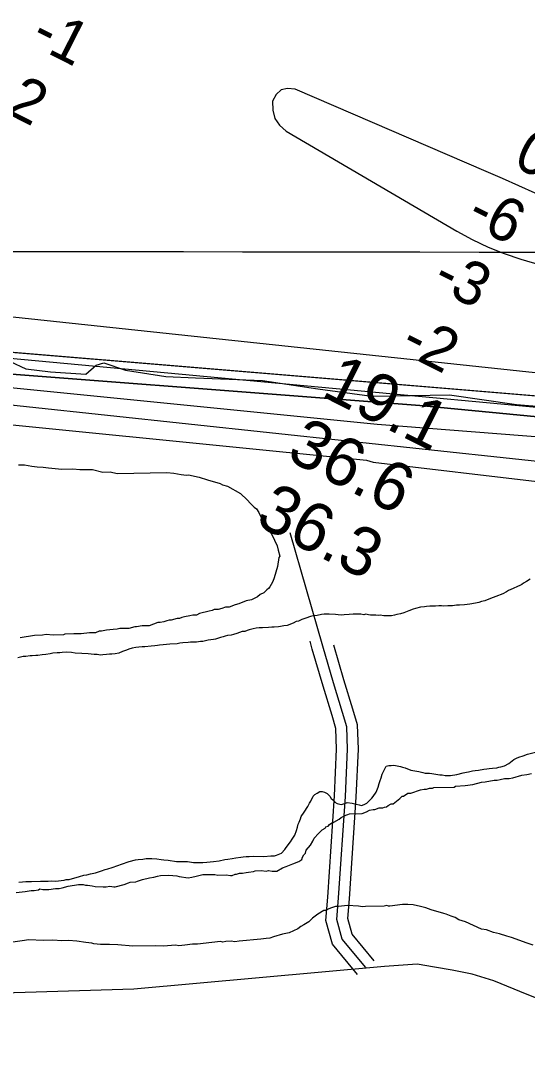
# Model space of a CAD drawing. Extents: x 3219052 to 3256913, y 800770 to 826146.
# Drawn here: x 3237159 to 3237861, y 811124 to 812545 of the extents above; entities that cross this region are included whole.
import ezdxf

# ---------------------------------------------------------------- set-up
doc = ezdxf.new("R2010")
doc.units = 0
for name, color, linetype in [('V-GRID-MAJR', 7, 'Continuous'), ('V-LEVE-TOET', 7, 'Continuous'), ('V-RIVR-EDGE', 7, 'Continuous'), ('V-RIVR-RANG', 7, 'Continuous'), ('V-ROAD-CNTR', 7, 'Continuous'), ('V-SITE-VEGE', 7, 'Continuous'), ('V-TOPO-DPTH', 7, 'Continuous'), ('V-TOPO-MAJR', 7, 'Continuous'), ('V-TOPO-MINR', 7, 'Continuous'), ('V-TOPO-SHOR', 7, 'Continuous'), ('V-TOPO-WATR', 7, 'Continuous')]:
    doc.layers.add(name, color=color, linetype=linetype)

msp = doc.modelspace()

# ---------------------------------------------------------------- linework, layer by layer
at = {"layer": 'V-GRID-MAJR'}
msp.add_spline([(3223229.222, 812245.659), (3228465.955, 812237.661), (3233702.6890000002, 812230.425), (3238939.4250000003, 812223.951), (3244176.161, 812218.238), (3249412.899, 812213.287), (3254649.637, 812209.098), (3254649.6380000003, 812209.098)], degree=3, dxfattribs=at)
at = {"layer": 'V-LEVE-TOET'}
msp.add_lwpolyline([(3238182.165, 811071.7000000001), (3237860.271, 811198.746), (3237814.414, 811217.536), (3237784.448, 811226.4720000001), (3237756.583, 811232.116), (3237732.015, 811236.265), (3237708.346, 811240.419), (3237688.88, 811239.188), (3237662.825, 811237.3470000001), (3237316.042, 811205.908), (3236864.697, 811191.961), (3236556.232, 811171.966), (3236455.3140000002, 811160.1140000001), (3236418.184, 811154.96), (3236209.219, 811099.193)], dxfattribs=at)
at = {"layer": 'V-RIVR-EDGE'}
msp.add_lwpolyline([(3237145.1445905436, 812073.8424826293), (3237166.85369583, 812063.7911809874), (3237200.7487915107, 812059.7952554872), (3237249.859715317, 812056.6310639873), (3237263.799459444, 812068.7676121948), (3237274.674971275, 812072.2181536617), (3237304.641855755, 812061.7117537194), (3237360.2600295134, 812053.3153214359), (3237401.5500003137, 812051.4745064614), (3237494.127502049, 812047.7681554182), (3237570.6026253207, 812036.2773955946), (3237645.3422669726, 812026.0949646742), (3237753.147419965, 812028.0017894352), (3237845.700200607, 812014.2978782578), (3237963.4749681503, 812004.8783922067)], dxfattribs=at)
at = {"layer": 'V-ROAD-CNTR'}
for points in [[(3237637.254688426, 811235.6885012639), (3237604.4487540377, 811275.151422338), (3237597.099768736, 811302.399367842), (3237599.44776404, 811332.0253085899), (3237608.93274507, 811472.38002788), (3237611.754739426, 811537.9258967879), (3237610.680741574, 811568.8178350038), (3237604.7837533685, 811588.630795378), (3237592.4097781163, 811629.3547139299), (3237577.4488080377, 811680.473611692), (3237532.3648982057, 811837.067298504)], [(3237625.7197114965, 811226.0995204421), (3237590.819781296, 811268.082436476), (3237581.9417990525, 811300.9983706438), (3237584.48779396, 811333.1233063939), (3237593.9547750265, 811473.2080262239), (3237596.7437694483, 811537.987896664), (3237595.7567714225, 811566.3788398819), (3237590.4187820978, 811584.310804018), (3237578.035806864, 811625.0677225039), (3237563.0438368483, 811676.2916200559), (3237559.9048431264, 811687.19459825)], [(3237648.7896653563, 811245.277482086), (3237618.07772678, 811282.2204082), (3237612.2577384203, 811303.8003650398), (3237614.4077341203, 811330.927310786), (3237623.9107151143, 811471.552029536), (3237626.765709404, 811537.8638969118), (3237625.6047117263, 811571.256830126), (3237619.148724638, 811592.950786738), (3237606.7837493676, 811633.641705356), (3237592.720777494, 811681.6946092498)]]:
    msp.add_lwpolyline(points, dxfattribs=at)
at = {"layer": 'V-SITE-VEGE'}
for points in [[(3237156.441, 811931.082), (3237164.6950000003, 811931.242), (3237175.0470000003, 811929.372), (3237182.289, 811928.479), (3237190.559, 811927.604), (3237197.798, 811926.709), (3237216.404, 811924.9990000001), (3237231.877, 811925.294), (3237241.179, 811924.438), (3237258.714, 811924.772), (3237273.232, 811920.924), (3237283.548, 811921.116), (3237292.8710000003, 811919.23), (3237361.978, 811920.545), (3237371.282, 811919.689), (3237381.6350000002, 811917.819), (3237388.877, 811916.9280000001), (3237391.969, 811916.988), (3237406.469, 811914.1680000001), (3237417.895, 811910.258), (3237435.526, 811905.433), (3237438.662, 811903.43), (3237445.92, 811901.503), (3237463.651, 811891.523), (3237473.111, 811882.415), (3237477.3340000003, 811877.336), (3237482.589, 811872.278), (3237485.725, 811870.273), (3237488.915, 811865.1730000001), (3237495.361, 811851.884), (3237498.572, 811845.752), (3237503.847, 811839.659), (3237507.04, 811834.564), (3237514.554, 811819.228), (3237515.703, 811813.06), (3237517.923, 811804.8470000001), (3237516.93, 811802.765), (3237515.103, 811790.348), (3237510.239, 811774.779), (3237508.275, 811769.581), (3237506.291, 811765.415), (3237504.286, 811762.282), (3237502.262, 811760.18), (3237500.239, 811758.077), (3237496.1920000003, 811753.875), (3237491.072, 811751.712), (3237487.007, 811748.54), (3237478.833, 811744.257), (3237471.632, 811743.088), (3237461.396, 811738.767), (3237456.258, 811737.636), (3237448.0640000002, 811734.386), (3237442.907, 811734.2880000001)], [(3237442.907, 811734.2880000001), (3237437.789, 811732.127), (3237432.653, 811730.996), (3237427.494, 811730.898), (3237424.42, 811729.809), (3237420.3140000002, 811728.701), (3237406.965, 811725.348), (3237402.877, 811723.208), (3237397.72, 811723.11), (3237393.614, 811722), (3237386.413, 811720.8300000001), (3237382.307, 811719.72), (3237379.233, 811718.631), (3237376.136, 811718.571), (3237367.926, 811716.351), (3237364.829, 811716.292), (3237361.755, 811715.202), (3237357.649, 811714.094), (3237352.5100000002, 811712.964), (3237349.418, 811712.904), (3237337.1180000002, 811708.544), (3237327.8340000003, 811708.366), (3237319.603, 811707.1780000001), (3237317.541, 811707.137), (3237309.326, 811704.919), (3237296.948, 811704.686), (3237292.842, 811703.576), (3237287.685, 811703.4770000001), (3237278.424, 811702.269), (3237271.221, 811701.1), (3237268.127, 811701.04), (3237263.009, 811698.88), (3237254.757, 811698.7220000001), (3237243.432, 811697.475), (3237237.2430000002, 811697.356), (3237233.116, 811697.28), (3237220.738, 811697.045), (3237218.694, 811695.974), (3237204.256, 811695.699), (3237194.952, 811696.555), (3237189.813, 811695.425), (3237178.467, 811695.212), (3237158.929, 811691.742)], [(3237774.687, 811487.794), (3237784.983, 811489.0210000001), (3237797.299, 811492.351), (3237802.458, 811492.4500000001), (3237814.7970000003, 811494.747), (3237818.924, 811494.8250000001), (3237823.0300000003, 811495.935), (3237829.199, 811497.084), (3237835.3880000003, 811497.203), (3237840.526, 811498.331), (3237852.843, 811501.661), (3237860.046, 811502.831), (3237866.214, 811503.98)], [(3237212.984, 811345.041), (3237217.091, 811346.149), (3237225.303, 811348.3690000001), (3237239.705, 811350.707), (3237245.894, 811350.824), (3237249.009, 811349.851), (3237252.1010000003, 811349.911), (3237258.311, 811348.997), (3237262.4560000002, 811348.0430000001), (3237273.822, 811347.228), (3237277.949, 811347.306), (3237283.085, 811348.436), (3237288.265, 811347.5), (3237290.325, 811347.541), (3237302.644, 811350.873), (3237308.794, 811353.052), (3237310.84, 811354.1240000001), (3237319.089, 811354.279), (3237321.131, 811355.35), (3237325.237, 811356.46), (3237328.311, 811357.55), (3237337.556, 811359.79), (3237343.727, 811360.939), (3237348.865, 811362.0700000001), (3237352.969, 811363.18), (3237364.3170000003, 811363.395), (3237375.682, 811362.578), (3237378.7970000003, 811361.609), (3237391.214, 811359.778), (3237396.352, 811360.909), (3237402.521, 811362.057), (3237411.7630000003, 811364.296), (3237428.268, 811364.609), (3237432.413, 811363.657), (3237443.759, 811363.872), (3237449.969, 811362.959), (3237452.031, 811362.997), (3237456.117, 811365.14), (3237458.179, 811365.179), (3237462.287, 811366.291), (3237466.41, 811366.366), (3237471.5500000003, 811367.497), (3237474.645, 811367.554), (3237481.846, 811368.724), (3237483.89, 811369.795), (3237492.139, 811369.952), (3237499.381, 811369.058), (3237502.455, 811370.147), (3237507.632, 811369.213), (3237513.821, 811369.3300000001), (3237521.995, 811373.6140000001), (3237527.113, 811375.777), (3237536.3370000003, 811379.0480000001), (3237544.529, 811382.2980000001), (3237548.596, 811385.47), (3237549.569, 811388.585), (3237551.574, 811391.719), (3237553.597, 811393.822), (3237554.5500000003, 811397.965), (3237560.602, 811405.3030000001), (3237563.596, 811410.519), (3237565.582, 811414.685), (3237571.6550000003, 811420.993), (3237576.713, 811426.248), (3237580.799, 811428.388), (3237581.792, 811430.471), (3237584.866, 811431.56), (3237586.89, 811433.664), (3237589.9450000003, 811435.785), (3237593.019, 811436.873), (3237600.163, 811441.137), (3237603.216, 811443.261), (3237609.346, 811446.474), (3237612.4220000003, 811447.564), (3237614.464, 811448.635), (3237632.001, 811448.966), (3237638.147, 811451.148), (3237642.237, 811453.29), (3237647.373, 811454.4180000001), (3237649.438, 811454.457), (3237655.588, 811456.638), (3237660.745, 811456.736), (3237662.787, 811457.81), (3237665.883, 811457.867), (3237667.907, 811459.968), (3237671.992, 811462.108), (3237675.0870000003, 811462.1680000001), (3237684.233, 811469.5650000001), (3237687.268, 811472.7170000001), (3237689.3310000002, 811472.758), (3237695.4420000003, 811477.001), (3237699.5670000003, 811477.079), (3237712.897, 811481.46), (3237718.035, 811482.588), (3237721.13, 811482.648), (3237725.236, 811483.758), (3237729.363, 811483.838), (3237731.407, 811484.909), (3237759.256, 811485.437), (3237761.299, 811486.508), (3237774.687, 811487.794)], [(3237153.238, 811339.775), (3237165.596, 811341.0430000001), (3237173.829, 811342.231), (3237177.953, 811342.311), (3237184.124, 811343.46), (3237186.168, 811344.531), (3237190.313, 811343.576), (3237198.562, 811343.734), (3237207.827, 811344.9400000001), (3237212.984, 811345.041)], [(3237868.66, 811266.703), (3237860.3510000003, 811269.639), (3237838.534, 811277.481), (3237832.306, 811279.427), (3237821.935, 811282.3250000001), (3237813.64, 811284.229), (3237804.281, 811288.18), (3237797.039, 811289.0750000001), (3237775.183, 811298.9770000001), (3237765.842, 811301.895), (3237760.624, 811304.892), (3237755.428, 811306.856), (3237748.147, 811309.813), (3237745.034, 811310.786), (3237727.403, 811315.611), (3237720.122, 811318.566), (3237712.862, 811320.491), (3237702.5100000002, 811322.359), (3237695.27, 811323.2540000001), (3237688.049, 811323.117), (3237670.553, 811320.721), (3237668.49, 811320.682), (3237666.407, 811321.6730000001), (3237662.301, 811320.563), (3237636.515, 811320.073), (3237632.3880000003, 811319.9940000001), (3237627.213, 811320.927), (3237611.72, 811321.665), (3237599.362, 811320.397), (3237595.235, 811320.319), (3237588.055, 811318.12), (3237580.8910000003, 811314.888), (3237578.8310000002, 811314.8470000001), (3237570.678, 811309.534), (3237563.555, 811304.24), (3237558.494, 811298.983), (3237551.355, 811294.721), (3237547.267, 811292.579), (3237543.198, 811289.407), (3237530.92, 811284.012), (3237521.6750000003, 811281.7760000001), (3237509.359, 811278.446), (3237504.239, 811276.283), (3237499.082, 811276.187), (3237491.881, 811275.017), (3237462.009, 811272.386), (3237455.838, 811271.237), (3237450.663, 811272.171), (3237443.4420000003, 811272.034), (3237439.333, 811270.921), (3237436.22, 811271.8960000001), (3237423.863, 811270.6290000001), (3237404.304, 811268.194), (3237397.083, 811268.056), (3237386.792, 811266.828), (3237378.557, 811265.64), (3237374.412, 811266.5920000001), (3237356.895, 811265.226), (3237345.531, 811266.0430000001), (3237314.588, 811265.4550000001), (3237293.917, 811267.127), (3237282.553, 811267.9400000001), (3237270.1750000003, 811267.706), (3237260.873, 811268.562), (3237257.756, 811269.535), (3237249.486, 811270.409), (3237237.071, 811272.236), (3237225.704, 811273.051), (3237216.421, 811272.875), (3237204.022, 811273.672), (3237190.614, 811273.4180000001), (3237170.9960000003, 811274.0750000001), (3237161.733, 811272.867)], [(3237161.733, 811272.867), (3237145.269, 811270.491)]]:
    msp.add_lwpolyline(points, dxfattribs=at)
at = {"layer": 'V-TOPO-DPTH'}
for points in [[(3237871.2860702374, 812306.889872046), (3237848.769443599, 812316.9319345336), (3237826.1908794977, 812326.8339513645), (3237803.5710237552, 812336.6426044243), (3237539.197465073, 812450.3088582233), (3237528.6887296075, 812451.3996545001), (3237519.7538974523, 812449.5196154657), (3237513.1799202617, 812443.1833234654), (3237508.1798463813, 812433.8761961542), (3237508.262267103, 812421.3684348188), (3237510.992795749, 812410.0607670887), (3237517.695486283, 812400.5532397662), (3237527.0462847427, 812392.2458060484), (3237763.096281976, 812254.1215265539), (3237784.4340683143, 812242.6459441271), (3237806.2327968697, 812232.2315838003), (3237828.7229387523, 812223.4090566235), (3237851.6740228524, 812215.6477515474), (3237905.268645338, 812199.6485995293)], [(3237871.2860702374, 812306.889872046), (3237848.769443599, 812316.9319345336), (3237826.1908794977, 812326.8339513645), (3237803.5710237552, 812336.6426044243), (3237539.197465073, 812450.3088582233), (3237528.6887296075, 812451.3996545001), (3237519.7538974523, 812449.5196154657), (3237513.1799202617, 812443.1833234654), (3237508.1798463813, 812433.8761961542), (3237508.262267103, 812421.3684348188), (3237510.992795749, 812410.0607670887), (3237517.695486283, 812400.5532397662), (3237527.0462847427, 812392.2458060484), (3237763.096281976, 812254.1215265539), (3237784.4340683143, 812242.6459441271), (3237806.2327968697, 812232.2315838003), (3237828.7229387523, 812223.4090566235), (3237851.6740228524, 812215.6477515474), (3237905.268645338, 812199.6485995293)], [(3238279.0662157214, 811992.5104605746), (3236263.3109329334, 812160.2666766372)], [(3236263.3109329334, 812160.2666766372), (3238476.978607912, 811976.0396943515), (3238492.181669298, 811971.6285749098), (3238507.4172200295, 811967.3272036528), (3239341.521306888, 811922.0926631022)], [(3239312.1153528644, 811904.4490034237), (3238520.5956911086, 811925.9982919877), (3238490.5360639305, 811933.7220217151), (3238460.533346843, 811941.6564453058), (3238119.1909138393, 811974.039931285), (3237711.6959470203, 812013.2851889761), (3236978.4446943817, 812069.2369252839)]]:
    msp.add_lwpolyline(points, dxfattribs=at)
at = {"layer": 'V-TOPO-MAJR'}
msp.add_lwpolyline([(3236976.675069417, 812003.5082032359), (3237637.9890776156, 811937.6883757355), (3237647.1975861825, 811934.9098504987), (3238351.6437120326, 811851.516588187), (3238356.5495229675, 811852.3458410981), (3238359.097209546, 811852.1997481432), (3238392.1202804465, 811846.9973430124), (3238402.8611950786, 811845.1131436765), (3238413.5483847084, 811842.9820019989), (3238424.154986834, 811840.4804468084), (3238434.7078639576, 811837.7319492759), (3239311.6855875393, 811840.4262749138)], dxfattribs=at)
at = {"layer": 'V-TOPO-MINR'}
for points in [[(3237871.2860702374, 812306.889872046), (3237848.769443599, 812316.9319345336), (3237826.1908794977, 812326.8339513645), (3237803.5710237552, 812336.6426044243), (3237539.197465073, 812450.3088582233), (3237528.6887296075, 812451.3996545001), (3237519.7538974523, 812449.5196154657), (3237513.1799202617, 812443.1833234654), (3237508.1798463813, 812433.8761961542), (3237508.262267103, 812421.3684348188), (3237510.992795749, 812410.0607670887), (3237517.695486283, 812400.5532397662), (3237527.0462847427, 812392.2458060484), (3237763.096281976, 812254.1215265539), (3237784.4340683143, 812242.6459441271), (3237806.2327968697, 812232.2315838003), (3237828.7229387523, 812223.4090566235), (3237851.6740228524, 812215.6477515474), (3237905.268645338, 812199.6485995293)], [(3237070.4625623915, 812144.2142284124), (3238468.788826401, 811995.0523872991), (3238476.280380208, 811992.6359333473), (3238483.788910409, 811990.274512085), (3238491.3229052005, 811987.9956398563), (3238498.873876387, 811985.7718003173), (3239351.2416748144, 811927.6004964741)], [(3237025.2740428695, 812089.4185243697), (3238493.201968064, 811953.2482152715), (3238517.201058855, 811946.7728898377), (3239329.4793078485, 811914.9830428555), (3239338.858920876, 811912.7954531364), (3239348.2552308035, 811910.6843577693), (3239357.676586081, 811908.6880039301), (3239367.114638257, 811906.7681444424), (3239471.7874726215, 811886.1397889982), (3239533.6872031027, 811874.678702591), (3239595.737061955, 811864.1705298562), (3239658.0121133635, 811855.0917276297), (3239720.437293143, 811846.9658390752), (3240170.7075255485, 811793.6118011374), (3240175.304957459, 811793.1094056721), (3240179.907297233, 811792.6628783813), (3240184.516998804, 811792.3001533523), (3240189.13160824, 811791.9932964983), (3240238.2444342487, 811789.1759900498), (3240267.426285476, 811787.77521553), (3240296.6176557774, 811786.7378840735), (3240325.82330469, 811786.2457172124), (3240355.0384726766, 811786.1169934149), (3240791.40437533, 811788.2684641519)], [(3236942.230676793, 812058.3951681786), (3237652.881814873, 811987.293061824), (3238427.650480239, 811926.8786856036), (3238432.2480299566, 811925.6817593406), (3238436.851338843, 811924.4157481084), (3238443.7453417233, 811922.5580999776), (3238450.6515960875, 811920.7482088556), (3238457.576227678, 811919.009953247), (3238464.5131107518, 811917.3194546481), (3239339.5213585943, 811881.3794800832)], [(3236978.4446943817, 812069.2369252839), (3237711.6959470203, 812013.2851889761), (3238119.1909138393, 811974.039931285), (3238460.533346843, 811941.6564453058), (3238490.5360639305, 811933.7220217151), (3238520.5956911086, 811925.9982919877), (3239312.1153528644, 811904.4490034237)], [(3236943.0259246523, 812035.7495556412), (3238400.420479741, 811879.8452404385), (3238429.331135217, 811875.239076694), (3239333.6498527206, 811861.6271375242), (3239361.4474915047, 811857.0846881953), (3239389.268618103, 811852.682627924), (3239803.3859657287, 811788.7659327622), (3239864.9200130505, 811779.8268367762), (3239926.5447105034, 811771.6176601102), (3239988.3053831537, 811764.5033624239), (3240050.156705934, 811758.118984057), (3240118.536101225, 811751.673519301), (3240146.281664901, 811749.3061256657), (3240174.0484149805, 811747.2670447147), (3240201.846944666, 811745.7204327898), (3240229.6666607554, 811744.5021335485), (3240678.498516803, 811728.8310884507)]]:
    msp.add_lwpolyline(points, dxfattribs=at)
at = {"layer": 'V-TOPO-SHOR'}
for points in [[(3237846.932, 811762.622), (3237840.973, 811759.933), (3237834.583, 811757.235), (3237831.613, 811755.462), (3237826.512, 811752.787), (3237817.134, 811749.175), (3237813.306, 811747.385), (3237809.468, 811746.025), (3237801.801, 811742.873), (3237797.094, 811741.925), (3237793.687, 811740.573), (3237788.982, 811739.625), (3237781.282, 811738.189), (3237773.565, 811737.6140000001), (3237766.7060000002, 811737.054), (3237762.416, 811736.973), (3237756.8510000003, 811736.008), (3237750.842, 811735.893), (3237744.836, 811735.781), (3237741.823, 811736.1510000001), (3237737.96, 811736.078), (3237733.676, 811735.568), (3237725.523, 811735.414), (3237721.23, 811735.3300000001), (3237718.234, 811734.845), (3237712.664, 811734.31), (3237705.829, 811732.463), (3237702.841, 811731.547), (3237696.876, 811729.286), (3237689.628, 811726.573), (3237684.932, 811725.197), (3237680.227, 811724.248), (3237676.809, 811723.3250000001), (3237672.535, 811722.385), (3237668.673, 811722.311), (3237665.668, 811722.2540000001), (3237662.236, 811722.188), (3237657.069, 811722.9500000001), (3237654.0640000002, 811722.893), (3237651.052, 811723.263), (3237647.619, 811723.2000000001), (3237643.757, 811723.126), (3237640.744, 811723.497), (3237637.295, 811724.289), (3237634.299, 811723.804), (3237630.42, 811724.588), (3237626.985, 811724.525), (3237622.6950000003, 811724.443), (3237619.69, 811724.386), (3237614.112, 811724.279), (3237607.253, 811723.72), (3237603.399, 811723.216), (3237598.67, 811723.556), (3237595.227, 811723.921), (3237586.63, 811724.615), (3237582.3370000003, 811724.533), (3237579.333, 811724.476), (3237575.9080000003, 811723.982), (3237569.924, 811722.579), (3237564.3540000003, 811722.045), (3237560.507, 811721.113), (3237554.109, 811718.846), (3237548.563, 811717.023), (3237543.884, 811714.787), (3237540.8880000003, 811714.299), (3237536.6380000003, 811712.073), (3237528.11, 811708.907), (3237523.828, 811708.395), (3237519.123, 811707.447), (3237516.127, 811706.961), (3237510.127, 811706.416), (3237507.122, 811706.359), (3237502.4020000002, 811706.2710000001), (3237494.257, 811705.685), (3237489.536, 811705.595), (3237485.252, 811705.085), (3237481.4050000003, 811704.153), (3237475.8510000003, 811702.761), (3237472.863, 811701.845), (3237469.883, 811700.5), (3237466.021, 811700.4280000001), (3237458.773, 811697.712), (3237454.079, 811696.336), (3237450.661, 811695.412), (3237445.518, 811694.884), (3237442.5300000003, 811693.971), (3237439.542, 811693.0530000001), (3237436.126, 811692.132), (3237429.3000000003, 811689.854), (3237426.304, 811689.3690000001), (3237419.025, 811688.371), (3237411.755, 811686.944), (3237408.321, 811686.88), (3237402.756, 811685.916), (3237399.324, 811685.85), (3237394.603, 811685.76), (3237391.179, 811685.267), (3237383.892, 811684.697), (3237379.608, 811684.187), (3237376.181, 811683.694), (3237365.89, 811683.067)], [(3237864.34, 811772.827), (3237859.6750000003, 811769.732), (3237855.426, 811767.5040000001), (3237852.884, 811765.741), (3237850.34, 811763.973), (3237846.932, 811762.622)], [(3237365.89, 811683.067), (3237356.893, 811682.039), (3237351.753, 811681.511), (3237348.756, 811681.025), (3237345.33, 811680.53), (3237340.181, 811680.431), (3237331.185, 811679.403), (3237327.752, 811679.338), (3237323.04, 811678.818), (3237318.755, 811678.308), (3237313.6210000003, 811677.351), (3237309.355, 811675.981), (3237305.9450000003, 811674.6290000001), (3237300.399, 811672.807), (3237295.289, 811670.562), (3237290.157, 811669.608), (3237285.4450000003, 811669.087), (3237282.44, 811669.03), (3237278.148, 811668.948), (3237273.005, 811668.422), (3237270.011, 811667.936), (3237265.274, 811668.704), (3237261.411, 811668.631), (3237257.102, 811669.409), (3237252.804, 811669.755), (3237244.2120000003, 811670.0210000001), (3237234.755, 811670.699), (3237230.018, 811671.469), (3237223.5700000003, 811671.7760000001), (3237217.134, 811671.654), (3237213.707, 811671.158), (3237209.847, 811671.084), (3237203.846, 811670.542), (3237200.428, 811669.618), (3237194.438, 811668.645), (3237189.295, 811668.1190000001), (3237183.294, 811667.574), (3237180.29, 811667.519), (3237175.578, 811666.9990000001), (3237172.573, 811666.941), (3237166.583, 811665.97), (3237163.148, 811665.905), (3237155.4560000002, 811664.041)], [(3237860.779, 811531.052), (3237873.597, 811534.3)], [(3237417.133, 811381.372), (3237426.56, 811382.41), (3237434.269, 811383.414), (3237441.961, 811385.28), (3237446.2430000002, 811385.79), (3237452.236, 811386.762), (3237457.3680000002, 811387.719), (3237464.219, 811388.706), (3237467.223, 811388.763), (3237471.507, 811389.275), (3237475.798, 811389.357), (3237482.2290000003, 811389.908), (3237495.977, 811389.31), (3237505.832, 811390.357), (3237510.553, 811390.447), (3237513.541, 811391.362), (3237520.358, 811394.068), (3237524.989, 811398.878), (3237527.078, 811401.924), (3237532.9390000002, 811409.762), (3237535.02, 811413.237), (3237538.776, 811418.889), (3237541.23, 811425.375), (3237542.428, 811430.121), (3237543.64, 811434.008), (3237544.8710000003, 811437.037), (3237546.935, 811441.368), (3237547.728, 811444.817), (3237551.906, 811450.908), (3237556.909, 811458.731), (3237558.973, 811463.063), (3237561.062, 811466.108), (3237564.366, 811473.041), (3237566.469, 811475.228), (3237569.8710000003, 811477.01), (3237573.262, 811479.219), (3237576.697, 811479.285), (3237580.146, 811478.492), (3237583.619, 811476.412), (3237587.117, 811473.045), (3237589.3310000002, 811469.6510000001), (3237591.5160000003, 811467.546), (3237594.148, 811464.591), (3237597.6210000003, 811462.51), (3237603.227, 811461.328), (3237607.923, 811462.706), (3237611.3310000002, 811464.058), (3237618.214, 811463.331), (3237623.825, 811461.719), (3237627.704, 811460.937), (3237631.153, 811460.142), (3237634.991, 811461.502), (3237638.393, 811463.286), (3237640.926, 811465.479), (3237645.5670000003, 811469.862), (3237647.234, 811472.469), (3237651.412, 811478.56), (3237654.293, 811485.054), (3237655.483, 811490.2270000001), (3237657.1180000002, 811494.5530000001), (3237658.34, 811498.01), (3237659.5300000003, 811503.185), (3237665.326, 811514.457), (3237668.742, 811515.381), (3237672.185, 811515.0160000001), (3237676.039, 811515.518), (3237685.083, 811513.974), (3237688.112, 811512.743), (3237691.563, 811511.951), (3237699.352, 811508.664), (3237710.5500000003, 811506.73), (3237716.1550000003, 811505.549), (3237719.174, 811504.748), (3237725.191, 811504.432), (3237728.634, 811504.0700000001), (3237739.394, 811502.556), (3237742.8370000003, 811502.192), (3237746.716, 811501.407), (3237750.578, 811501.481), (3237754.441, 811501.555), (3237762.999, 811503.005), (3237771.98, 811504.893), (3237776.254, 811505.833), (3237779.25, 811506.319), (3237784.804, 811507.713), (3237788.659, 811508.215), (3237792.941, 811508.7270000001), (3237800.213, 811510.152), (3237804.498, 811510.662), (3237807.9220000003, 811511.158), (3237812.207, 811511.6680000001), (3237818.205, 811512.213), (3237821.193, 811513.126), (3237824.1890000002, 811513.6140000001), (3237828.8850000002, 811514.992), (3237834.8370000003, 811518.109), (3237842.036, 811523.399), (3237845.427, 811525.609), (3237848.835, 811526.962), (3237854.811, 811528.791), (3237860.779, 811531.052)], [(3237157.055, 811354.103), (3237162.2060000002, 811354.201), (3237166.489, 811354.711), (3237174.644, 811354.867), (3237187.089, 811355.1020000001), (3237191.382, 811355.184), (3237197.389, 811355.299), (3237202.1010000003, 811355.817), (3237207.688, 811355.496), (3237219.6890000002, 811356.581), (3237222.677, 811357.497), (3237226.538, 811357.5700000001), (3237241.058, 811361.709), (3237247.032, 811363.54), (3237250.889, 811364.044), (3237256.0130000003, 811365.4280000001), (3237262.855, 811366.848), (3237271.389, 811369.586), (3237276.507, 811371.4), (3237279.923, 811372.324), (3237286.329, 811374.1630000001), (3237294.005, 811376.885), (3237299.1210000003, 811378.7000000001), (3237309.785, 811382.337), (3237318.327, 811384.645), (3237322.184, 811385.149), (3237328.612, 811385.7000000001), (3237333.3170000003, 811386.648), (3237341.042, 811386.795), (3237347.9250000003, 811386.066), (3237353.948, 811385.323), (3237357.3910000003, 811384.958), (3237363.414, 811384.215), (3237375.034, 811382.718), (3237381.051, 811382.402), (3237385.344, 811382.484), (3237390.4930000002, 811382.583), (3237398.681, 811381.022), (3237406.8340000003, 811381.176), (3237411.554, 811381.2660000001), (3237417.133, 811381.372)]]:
    msp.add_lwpolyline(points, dxfattribs=at)
at = {"layer": 'V-TOPO-WATR'}
msp.add_lwpolyline([(3236263.3109329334, 812160.2666766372), (3238476.978607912, 811976.0396943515), (3238492.181669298, 811971.6285749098), (3238507.4172200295, 811967.3272036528), (3239341.521306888, 811922.0926631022)], dxfattribs=at)

# ---------------------------------------------------------------- texts
at = {"layer": 'V-RIVR-RANG'}
for s, height, rotation, p in [('-1', 60, 333.05116666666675, (3237170.8608257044, 812513.4308678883)), ('-2', 60, 333.05116666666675, (3237112.9659366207, 812430.6872603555)), ('0', 60, 333.15536111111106, (3237839.0240555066, 812345.3323387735)), ('-6', 60, 333.15536111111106, (3237773.8579474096, 812266.237400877)), ('-3', 60, 333.15536111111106, (3237726.607779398, 812178.0744497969)), ('-2', 60, 333.15536111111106, (3237682.3083074, 812088.4181083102)), ('19.1', 67.00000000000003, 333.28832571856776, (3237573.6833583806, 812027.0931283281)), ('36.6', 67.00000000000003, 333.28832571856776, (3237525.1922955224, 811939.5472349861)), ('36.3', 67.00000000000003, 333.28832571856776, (3237482.1206980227, 811849.2742508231))]:
    msp.add_text(s, height=height, rotation=rotation, dxfattribs=at).set_placement(p)

doc.saveas('drawing.dxf')
